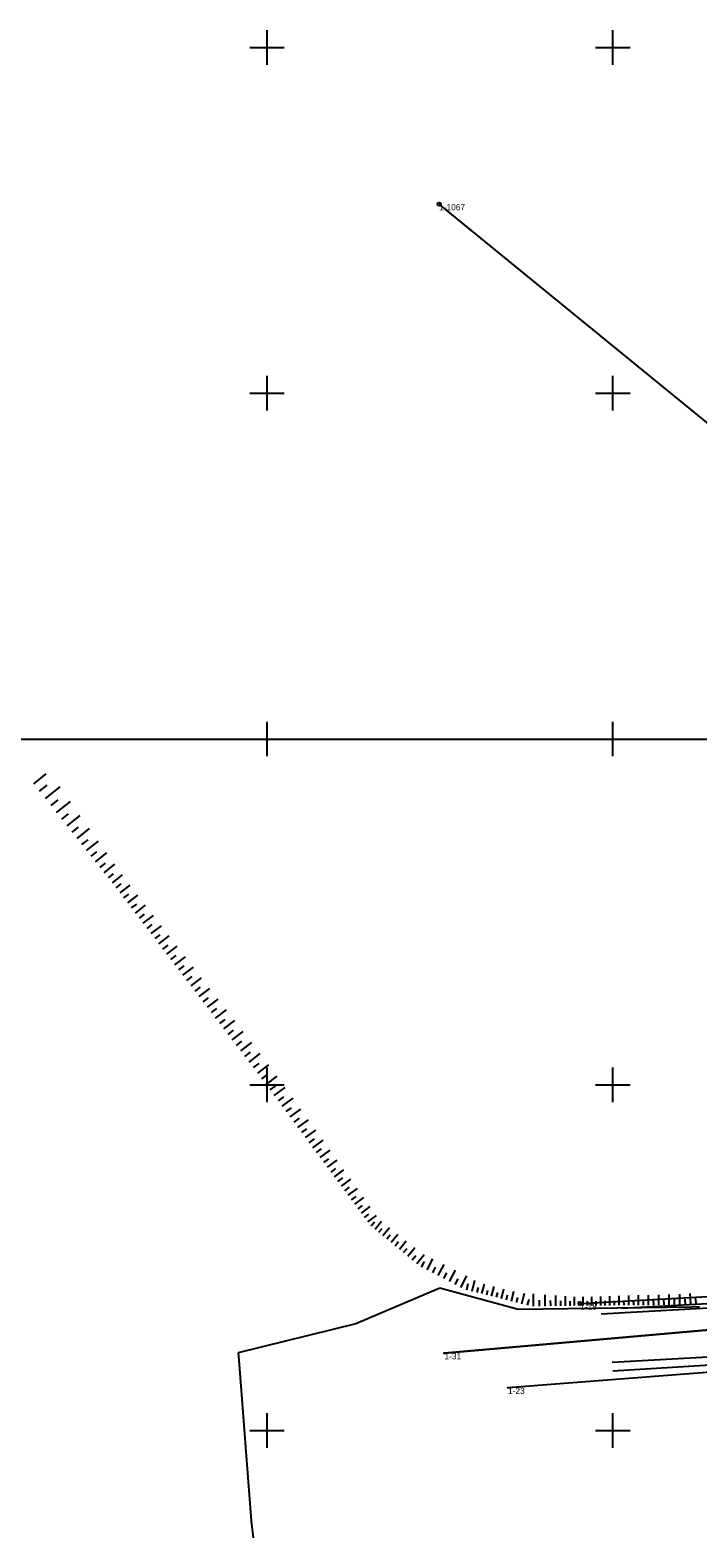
# Model space of a CAD drawing. Extents: x 5598798 to 5599616, y 5661498 to 5662453.
# Drawn here: x 5599015.8 to 5599112.3, y 5661884.5 to 5662102.5 of the extents above; entities that cross this region are included whole.
import ezdxf

# ---------------------------------------------------------------- set-up
doc = ezdxf.new("R2010")
doc.units = 0
for name, color, linetype in [('BUBZ_L_1', 7, 'Continuous'), ('Dzialki', 7, 'Continuous'), ('Kontury', 7, 'Continuous'), ('KTJZ_L_0', 7, 'Continuous'), ('KTKR_L_0', 7, 'Continuous'), ('KTOK_L_4', 7, 'Continuous'), ('Numery_punktow', 7, 'Continuous'), ('Podzial_sekcyjny_krzyze', 7, 'Continuous'), ('Podzial_sekcyjny_podstawowy', 7, 'Continuous'), ('Punkty', 7, 'Continuous'), ('SUPW_L_0', 7, 'Continuous'), ('Uzytki', 7, 'Continuous')]:
    doc.layers.add(name, color=color, linetype=linetype)

# ---------------------------------------------------------------- blocks, each defined once
blk = doc.blocks.new('GRO')
blk.add_circle((0, 0), 0.045)
blk = doc.blocks.new('GRT')
blk.add_circle((0, 0), 0.25)

msp = doc.modelspace()

# ---------------------------------------------------------------- linework, layer by layer
at = {"layer": 'BUBZ_L_1'}
for p, q in [((5599016.283681, 5661993.540689), (5599018.067169, 5661994.953101)), ((5599017.140903, 5661992.458252), (5599018.223339, 5661993.315475)), ((5599017.976103, 5661991.403623), (5599020.085362, 5661993.074024)), ((5599018.789848, 5661990.376087), (5599019.817385, 5661991.189831)), ((5599019.582688, 5661989.374947), (5599021.584968, 5661990.960627)), ((5599020.355161, 5661988.399526), (5599021.330582, 5661989.171999)), ((5599021.107789, 5661987.449163), (5599023.008514, 5661988.954419)), ((5599021.841082, 5661986.523215), (5599022.767031, 5661987.256508)), ((5599022.555538, 5661985.621054), (5599024.35986, 5661987.049964)), ((5599023.251639, 5661984.742068), (5599024.130624, 5661985.43817)), ((5599023.929858, 5661983.885664), (5599025.642667, 5661985.242102)), ((5599024.590654, 5661983.05126), (5599025.425058, 5661983.712056)), ((5599025.234474, 5661982.238291), (5599026.860411, 5661983.525932)), ((5599025.861755, 5661981.446207), (5599026.653839, 5661982.073488)), ((5599026.472922, 5661980.674472), (5599028.016393, 5661981.896805)), ((5599027.068387, 5661979.922562), (5599027.820298, 5661980.518028)), ((5599027.648556, 5661979.189968), (5599029.113744, 5661980.350305)), ((5599028.213821, 5661978.476194), (5599028.927594, 5661979.041458)), ((5599028.767363, 5661977.754058), (5599030.214386, 5661978.857603)), ((5599029.320964, 5661977.02815), (5599030.046872, 5661977.581751)), ((5599029.876398, 5661976.299838), (5599031.333023, 5661977.410706)), ((5599030.433672, 5661975.569113), (5599031.164397, 5661976.126387)), ((5599030.992792, 5661974.835968), (5599032.459082, 5661975.954207)), ((5599031.553763, 5661974.100394), (5599032.289337, 5661974.661366)), ((5599032.116593, 5661973.362384), (5599033.592614, 5661974.488044)), ((5599032.681288, 5661972.621929), (5599033.421742, 5661973.186624)), ((5599033.247852, 5661971.879022), (5599034.733667, 5661973.012151)), ((5599033.816294, 5661971.133654), (5599034.561662, 5661971.702095)), ((5599034.386618, 5661970.385817), (5599035.882292, 5661971.526465)), ((5599034.958832, 5661969.635503), (5599035.709146, 5661970.207716)), ((5599035.53294, 5661968.882703), (5599037.038539, 5661970.030921)), ((5599036.108951, 5661968.12741), (5599036.864244, 5661968.70342)), ((5599036.686869, 5661967.369615), (5599038.202459, 5661968.525452)), ((5599037.266702, 5661966.60931), (5599038.027007, 5661967.189143)), ((5599037.848455, 5661965.846487), (5599039.374102, 5661967.009994)), ((5599038.432136, 5661965.081137), (5599039.197486, 5661965.664817)), ((5599039.017749, 5661964.313252), (5599040.55352, 5661965.484479)), ((5599039.605303, 5661963.542823), (5599040.375731, 5661964.130376)), ((5599040.194802, 5661962.769842), (5599041.740764, 5661963.948841)), ((5599040.786255, 5661961.994301), (5599041.561796, 5661962.585753)), ((5599041.379666, 5661961.216191), (5599042.935886, 5661962.403014)), ((5599041.975043, 5661960.435504), (5599042.75573, 5661961.030881)), ((5599042.572392, 5661959.652231), (5599044.138938, 5661960.846929)), ((5599043.17172, 5661958.866363), (5599043.957587, 5661959.465691)), ((5599043.773032, 5661958.077892), (5599045.349974, 5661959.280518)), ((5599044.376337, 5661957.28681), (5599045.16742, 5661957.890114)), ((5599044.98164, 5661956.493107), (5599046.569046, 5661957.703713)), ((5599045.588948, 5661955.696775), (5599046.38528, 5661956.304083)), ((5599046.198268, 5661954.897805), (5599047.796207, 5661956.116444)), ((5599046.809606, 5661954.096189), (5599047.611222, 5661954.707527)), ((5599047.422969, 5661953.291918), (5599049.031511, 5661954.518644)), ((5599048.038363, 5661952.484982), (5599048.845299, 5661953.100377)), ((5599048.655796, 5661951.675374), (5599050.275013, 5661952.91024)), ((5599049.272514, 5661950.866605), (5599050.089912, 5661951.471841)), ((5599049.872114, 5661950.05682), (5599051.491683, 5661951.25602)), ((5599050.466129, 5661949.254578), (5599051.268372, 5661949.848593)), ((5599051.054612, 5661948.459807), (5599052.644153, 5661949.636773)), ((5599051.637614, 5661947.672439), (5599052.424982, 5661948.255441)), ((5599052.215186, 5661946.892404), (5599053.775256, 5661948.047548)), ((5599052.787379, 5661946.119633), (5599053.560149, 5661946.691826)), ((5599053.354242, 5661945.354061), (5599054.885388, 5661946.487788)), ((5599053.915826, 5661944.595618), (5599054.674269, 5661945.157202)), ((5599054.47218, 5661943.844239), (5599055.974937, 5661944.956946)), ((5599055.023351, 5661943.099859), (5599055.767732, 5661943.651031)), ((5599055.56939, 5661942.362411), (5599057.044285, 5661943.454488)), ((5599056.110343, 5661941.631832), (5599056.840922, 5661942.172784)), ((5599056.646257, 5661940.908057), (5599058.093807, 5661941.979886)), ((5599057.177181, 5661940.191023), (5599057.894215, 5661940.721946)), ((5599057.703159, 5661939.480667), (5599059.123871, 5661940.532624)), ((5599058.224239, 5661938.776927), (5599058.927978, 5661939.298007)), ((5599058.740465, 5661938.079742), (5599060.134836, 5661939.112195)), ((5599059.251884, 5661937.389049), (5599059.942576, 5661937.900468)), ((5599059.758539, 5661936.70479), (5599061.127057, 5661937.718101)), ((5599060.260476, 5661936.026904), (5599060.938362, 5661936.52884)), ((5599060.757737, 5661935.355331), (5599062.100883, 5661936.349855)), ((5599061.250368, 5661934.690013), (5599061.915686, 5661935.182644)), ((5599061.73841, 5661934.030892), (5599063.056653, 5661935.006976)), ((5599062.221907, 5661933.377909), (5599062.874889, 5661933.861406)), ((5599062.7009, 5661932.731009), (5599063.994702, 5661933.688996)), ((5599063.175433, 5661932.090133), (5599063.816308, 5661932.564665)), ((5599063.645545, 5661931.455226), (5599064.915359, 5661932.395451)), ((5599064.11128, 5661930.826232), (5599064.740273, 5661931.291966)), ((5599064.572676, 5661930.203097), (5599065.818947, 5661931.12589)), ((5599065.052691, 5661929.603575), (5599065.543182, 5661930.198461)), ((5599065.613618, 5661929.141084), (5599066.5386, 5661930.262937)), ((5599066.181532, 5661928.672832), (5599066.649784, 5661929.240746)), ((5599066.75652, 5661928.198747), (5599067.70469, 5661929.348723)), ((5599067.928073, 5661927.232787), (5599068.900011, 5661928.411591)), ((5599067.338671, 5661927.718756), (5599067.818661, 5661928.300907)), ((5599068.524817, 5661926.740764), (5599069.016839, 5661927.337508)), ((5599069.128994, 5661926.242612), (5599070.125297, 5661927.450967)), ((5599069.740697, 5661925.738255), (5599070.245054, 5661926.349959)), ((5599070.36002, 5661925.227616), (5599071.381299, 5661926.466262)), ((5599070.987057, 5661924.710616), (5599071.504058, 5661925.337653)), ((5599071.635109, 5661924.176289), (5599072.703762, 5661925.472392)), ((5599072.351588, 5661923.650398), (5599072.762173, 5661924.443037)), ((5599073.148418, 5661923.237643), (5599073.973929, 5661924.831303)), ((5599074.754739, 5661922.405573), (5599075.589003, 5661924.01613)), ((5599073.949461, 5661922.822705), (5599074.364399, 5661923.623748)), ((5599075.564275, 5661921.986236), (5599075.983612, 5661922.795772)), ((5599076.378091, 5661921.564682), (5599077.2212, 5661923.192314)), ((5599077.19621, 5661921.140899), (5599077.619993, 5661921.959018)), ((5599078.018655, 5661920.714875), (5599078.870702, 5661922.359764)), ((5599078.857976, 5661920.366656), (5599079.083151, 5661921.25277)), ((5599079.655514, 5661920.16399), (5599080.060846, 5661921.759065)), ((5599080.373329, 5661919.981582), (5599080.555737, 5661920.699398)), ((5599081.062394, 5661919.80648), (5599081.412598, 5661921.184611)), ((5599081.757089, 5661919.629948), (5599081.933621, 5661920.324642)), ((5599082.457458, 5661919.451973), (5599082.813407, 5661920.852712)), ((5599083.163549, 5661919.272545), (5599083.342977, 5661919.978635)), ((5599083.875408, 5661919.09165), (5599084.237196, 5661920.515368)), ((5599085.316619, 5661918.725417), (5599085.684342, 5661920.17249)), ((5599086.816084, 5661918.34438), (5599087.20743, 5661919.884416)), ((5599088.539569, 5661917.98416), (5599088.513726, 5661919.782797)), ((5599108.142054, 5661918.175152), (5599108.130883, 5661919.693386)), ((5599109.685676, 5661918.18651), (5599109.674256, 5661919.738658)), ((5599111.247839, 5661918.265367), (5599111.14, 5661919.821914)), ((5599084.593082, 5661918.909279), (5599084.775454, 5661919.626953)), ((5599086.046066, 5661918.540053), (5599086.23143, 5661919.269501)), ((5599087.658972, 5661918.130189), (5599087.873162, 5661918.973077)), ((5599089.399229, 5661917.996512), (5599089.386878, 5661918.856173)), ((5599090.220982, 5661918.008319), (5599090.197368, 5661919.651823)), ((5599091.006497, 5661918.019605), (5599090.995211, 5661918.80512)), ((5599091.757374, 5661918.030393), (5599091.735797, 5661919.532146)), ((5599092.475139, 5661918.040706), (5599092.464826, 5661918.758471)), ((5599093.161252, 5661918.050564), (5599093.141536, 5661919.422791)), ((5599093.81711, 5661918.059987), (5599093.807687, 5661918.715845)), ((5599094.444047, 5661918.068995), (5599094.426032, 5661919.322868)), ((5599095.059851, 5661918.077843), (5599095.051003, 5661918.693646)), ((5599095.682079, 5661918.083473), (5599095.672922, 5661919.327952)), ((5599096.31123, 5661918.088103), (5599096.3066, 5661918.717254)), ((5599096.947369, 5661918.092783), (5599096.938007, 5661919.365062)), ((5599097.590574, 5661918.097516), (5599097.585841, 5661918.740721)), ((5599098.240923, 5661918.102301), (5599098.231353, 5661919.403)), ((5599098.898496, 5661918.107139), (5599098.893658, 5661918.764712)), ((5599099.563373, 5661918.112032), (5599099.553589, 5661919.441785)), ((5599100.235635, 5661918.116978), (5599100.230688, 5661918.78924)), ((5599100.915364, 5661918.121979), (5599100.905361, 5661919.481437)), ((5599101.602643, 5661918.127036), (5599101.597586, 5661918.814315)), ((5599102.297556, 5661918.132149), (5599102.287329, 5661919.521975)), ((5599103.000187, 5661918.137319), (5599102.995017, 5661918.839951)), ((5599103.710623, 5661918.142546), (5599103.700169, 5661919.563418)), ((5599104.42895, 5661918.147832), (5599104.423665, 5661918.866159)), ((5599105.155256, 5661918.153176), (5599105.144568, 5661919.605787)), ((5599105.889629, 5661918.158579), (5599105.884226, 5661918.892952)), ((5599106.632159, 5661918.164043), (5599106.621232, 5661919.649103)), ((5599107.382937, 5661918.169567), (5599107.377413, 5661918.920344)), ((5599108.909602, 5661918.1808), (5599108.903955, 5661918.948348)), ((5599110.469566, 5661918.211447), (5599110.415335, 5661918.994215)), ((5599112.021645, 5661918.318977), (5599111.968035, 5661919.092782))]:
    msp.add_line(p, q, dxfattribs=at)
at = {"layer": 'Dzialki'}
for p, q in [((5599186.52, 5661986.2), (5599074.88, 5662077.34)), ((5599095.27, 5661918.37), (5599179.08, 5661922.96)), ((5599181.23, 5661920.49), (5599075.65, 5661911.2)), ((5599180.64, 5661913.54), (5599084.84, 5661906.2))]:
    msp.add_line(p, q, dxfattribs=at)
at = {"layer": 'Kontury'}
for p, q in [((5599186.52, 5661986.2), (5599074.88, 5662077.34)), ((5599075.65, 5661911.2), (5599181.23, 5661920.49))]:
    msp.add_line(p, q, dxfattribs=at)
at = {"layer": 'KTJZ_L_0'}
for p, q in [((5599098.3, 5661916.91), (5599175.3, 5661921.09)), ((5599174.91, 5661913.97), (5599099.89, 5661909.87))]:
    msp.add_line(p, q, dxfattribs=at)
at = {"layer": 'KTKR_L_0'}
for p, q in [((5599098.3, 5661916.91), (5599175.3, 5661921.09)), ((5599174.91, 5661913.97), (5599099.89, 5661909.87))]:
    msp.add_line(p, q, dxfattribs=at)
at = {"layer": 'KTOK_L_4'}
for p, q in [((5599164.73, 5661920.98), (5599101.3, 5661917.68)), ((5599099.97, 5661908.66), (5599165.02, 5661912.62))]:
    msp.add_line(p, q, dxfattribs=at)
at = {"layer": 'Podzial_sekcyjny_krzyze'}
for p, q in [((5599050, 5662097.5), (5599050, 5662102.5)), ((5599100, 5662097.5), (5599100, 5662102.5)), ((5599047.5, 5662100), (5599052.5, 5662100)), ((5599097.5, 5662100), (5599102.5, 5662100)), ((5599050, 5662047.5), (5599050, 5662052.5)), ((5599100, 5662047.5), (5599100, 5662052.5)), ((5599047.5, 5662050), (5599052.5, 5662050)), ((5599097.5, 5662050), (5599102.5, 5662050)), ((5599050, 5661997.5), (5599050, 5662002.5)), ((5599100, 5661997.5), (5599100, 5662002.5)), ((5599047.5, 5662000), (5599052.5, 5662000)), ((5599097.5, 5662000), (5599102.5, 5662000)), ((5599050, 5661947.5), (5599050, 5661952.5)), ((5599100, 5661947.5), (5599100, 5661952.5)), ((5599047.5, 5661950), (5599052.5, 5661950)), ((5599097.5, 5661950), (5599102.5, 5661950)), ((5599050, 5661897.5), (5599050, 5661902.5)), ((5599100, 5661897.5), (5599100, 5661902.5)), ((5599047.5, 5661900), (5599052.5, 5661900)), ((5599097.5, 5661900), (5599102.5, 5661900))]:
    msp.add_line(p, q, dxfattribs=at)
at = {"layer": 'Podzial_sekcyjny_podstawowy'}
msp.add_line((5598800, 5662000), (5599200, 5662000), dxfattribs=at)
at = {"layer": 'SUPW_L_0'}
for p, q in [((5599074.985221, 5661920.609847), (5599062.837336, 5661915.422693)), ((5599086.310807, 5661917.521899), (5599074.985221, 5661920.609847)), ((5599111.350794, 5661917.843512), (5599086.310807, 5661917.521899)), ((5599112.517084, 5661917.916406), (5599111.350794, 5661917.843512)), ((5599062.837336, 5661915.422693), (5599045.843092, 5661911.231488)), ((5599045.843092, 5661911.231488), (5599045.919022, 5661910.198836)), ((5599045.919022, 5661910.198836), (5599047.703282, 5661886.971456)), ((5599047.703282, 5661886.971456), (5599047.981851, 5661884.495312))]:
    msp.add_line(p, q, dxfattribs=at)
at = {"layer": 'Uzytki'}
for p, q in [((5599186.52, 5661986.2), (5599074.88, 5662077.34)), ((5599095.27, 5661918.37), (5599179.08, 5661922.96)), ((5599075.65, 5661911.2), (5599181.23, 5661920.49))]:
    msp.add_line(p, q, dxfattribs=at)

# ---------------------------------------------------------------- block references
at = {"layer": 'Punkty'}
for name, p in [('GRT', (5599074.88, 5662077.34)), ('GRT', (5599095.27, 5661918.37)), ('GRO', (5599075.65, 5661911.2)), ('GRO', (5599084.84, 5661906.2))]:
    msp.add_blockref(name, p, dxfattribs=at)

# ---------------------------------------------------------------- texts
at = {"layer": 'Numery_punktow'}
for s, p in [('1-1067', (5599074.88, 5662076.44)), ('1-18', (5599095.27, 5661917.47)), ('1-31', (5599075.65, 5661910.3)), ('1-23', (5599084.84, 5661905.3))]:
    msp.add_text(s, height=0.9, dxfattribs=at).set_placement(p)

doc.saveas('drawing.dxf')
